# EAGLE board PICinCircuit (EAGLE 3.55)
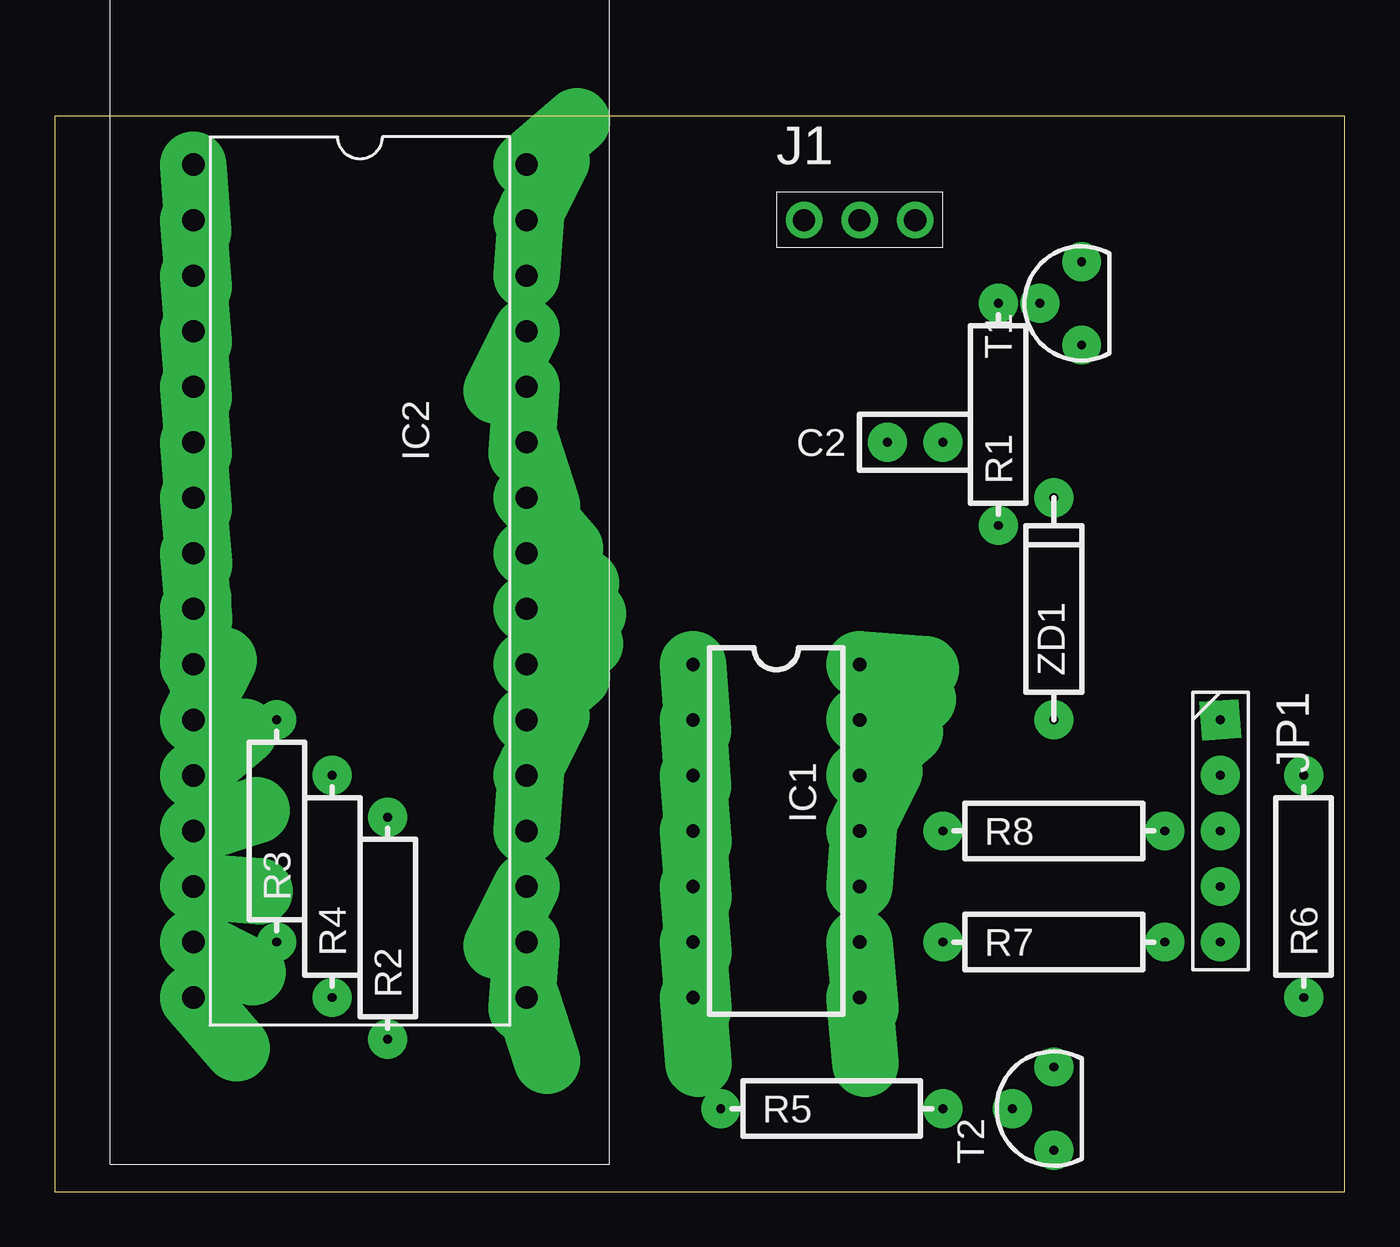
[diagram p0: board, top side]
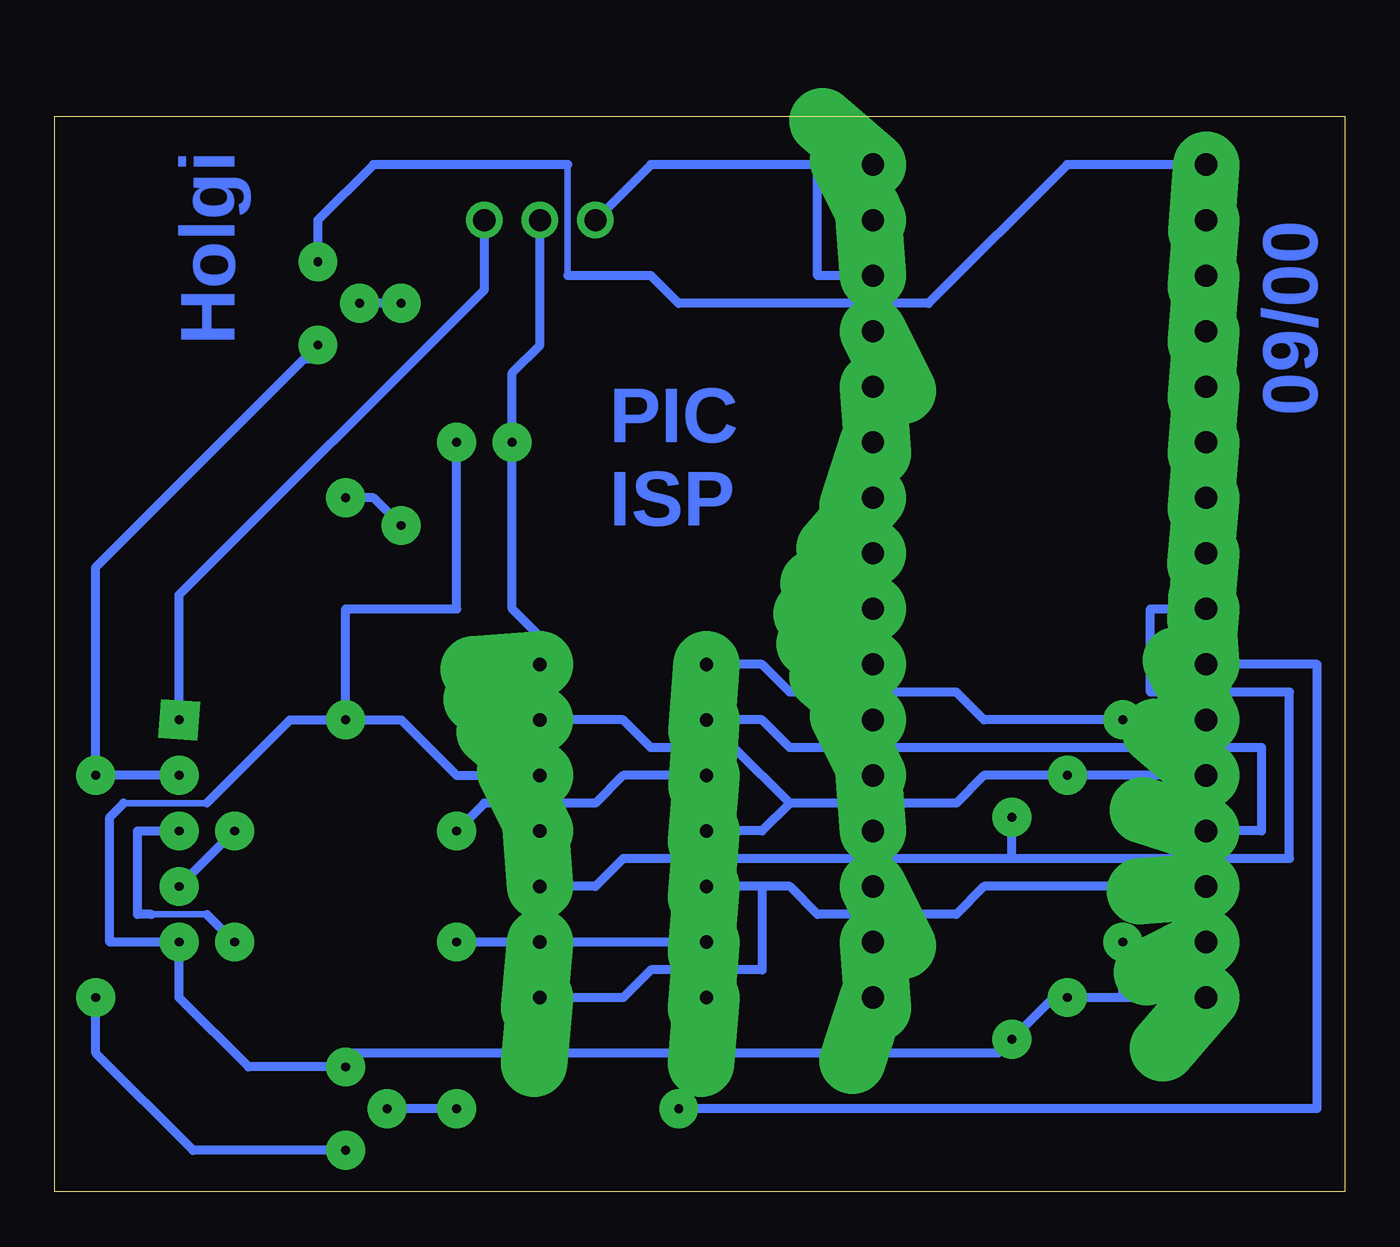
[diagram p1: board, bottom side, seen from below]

Size 59.03 x 49.2 mm. Coordinates in mm from the lower left corner, seen from the top.
Outline: 0,0 59.03,0 59.03,49.2 0,49.2 0,0
Copper layers used: Bottom

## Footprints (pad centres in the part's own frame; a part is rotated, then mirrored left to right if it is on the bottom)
RM2,5 = drill 0.406 pad 1.778 round:  0,0;  2.54,0
L-14B = drill 0.61 pad 3.048 offset:  0,0;  2.54,0;  5.08,0;  7.62,0;  10.16,0;  12.7,0;  15.24,0;  15.24,7.62;  12.7,7.62;  10.16,7.62;  7.62,7.62;  5.08,7.62;  2.54,7.62;  0,7.62
XTO_32 = drill 1.016 pad 3.048 offset:  0,0;  2.54,0;  15.24,0;  17.78,0;  5.08,0;  7.62,0;  12.7,0;  10.16,0;  20.32,0;  22.86,0;  25.4,0;  27.94,0;  30.48,0;  33.02,0;  35.56,0;  38.1,0;  38.1,15.24;  35.56,15.24;  33.02,15.24;  30.48,15.24;  27.94,15.24;  25.4,15.24;  22.86,15.24;  20.32,15.24;  17.78,15.24;  15.24,15.24;  12.7,15.24;  10.16,15.24;  7.62,15.24;  5.08,15.24;  2.54,15.24;  0,15.24
MPER_3 = drill 1.016 pad 1.676 round:  0,0;  2.54,0;  5.08,0
5 = drill 0.406 pad 1.778 square:  0,0 | drill 0.406 pad 1.778 round:  5.08,0;  10.16,0;  7.62,0;  2.54,0
S04 = drill 0.406 pad 1.778 round:  0,0;  10.16,0
92 = drill 0.406 pad 1.778 round:  -0.635,0;  1.27,1.905;  3.175,0
O04 = drill 0.406 pad 1.778 round:  0,0;  10.16,0

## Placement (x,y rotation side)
C2  100n  [RM2,5]  40.64,34.29 180 top
IC1  74HC126  [L-14B]  29.21,24.13 270 top
IC2  TEXTOEP_32  [XTO_32]  6.35,46.99 270 top
J1  JUMPER_3  [MPER_3]  34.29,44.45 0 top
JP1  PINHD-1X5  [5]  53.34,21.59 270 top
R1  10k  [S04]  43.18,30.48 90 top
R2  47k  [S04]  15.24,6.99 90 top
R3  47k  [S04]  10.16,11.43 90 top
R4  47k  [S04]  12.7,8.89 90 top
R5  10k  [S04]  30.48,3.81 0 top
R6  470  [S04]  57.15,8.89 90 top
R7  220  [S04]  40.64,11.43 0 top
R8  220  [S04]  40.64,16.51 0 top
T1  BC327  [92]  46.99,39.37 90 top
T2  BC547  [92]  45.72,2.54 90 top
ZD1  8v2  [O04]  45.72,21.59 90 top

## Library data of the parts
C2 IC1 JP1 R1-R8 T1 T2 ZD1 = holg_plt
IC2 = galeprom
J1 = holgnorm

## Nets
5V_EXT: J1. JP1.
5V_INT: IC2. J1.
+5V: C2. IC1. J1.
GND: C2. IC1. IC2. JP1. R2. R3. R4. T2. ZD1.
MCLR: JP1. R6. T1.
N$1: IC1. IC2. R2.
N$2: R6. T2.
N$3: IC1. IC2. R3.
N$4: IC1. IC2. R4.
N$5: R5. T2.
N$6: JP1. R8.
N$7: R1. T1.
N$8: R1. ZD1.
N$9: IC2. R5.
N$10: JP1. R7.
PB6: IC1. R8.
PB7: IC1. R7.
SCK: IC1. IC2.
SDA: IC1. IC2.
VPP: IC2. T1.

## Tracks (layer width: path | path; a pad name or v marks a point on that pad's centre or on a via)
5V_EXT
  Bottom 0.406: J1. 39.37,41.27 53.34,27.3 53.34,21.59
5V_INT
  Bottom 0.406: 34.29,44.45 31.75,46.99 24.13,46.99 | 24.13,46.99 IC2. | 24.13,46.99 24.13,41.91 21.59,41.91
+5V
  Bottom 0.406: IC1. 36.83,25.4 38.1,26.67 C2. 38.1,37.47 36.83,38.73 36.83,44.45
GND
  Bottom 0.305: 55.88,17.78 52.07,17.78
  Bottom 0.406: 40.64,34.29 40.64,26.67 45.72,26.67 45.72,21.59 | 55.88,17.78 56.52,17.14 56.52,11.43 53.34,11.43 53.34,8.89 50.16,5.71 T2. 45.72,6.35 29.21,6.35 | 29.21,6.35 29.21,8.89 | 6.35,8.89 10.16,8.89 | 10.16,8.89 10.16,11.43 | 10.16,8.89 12.7,8.89 13.34,8.89 15.24,6.99 15.88,6.35 29.21,6.35 | 52.07,17.78 48.26,21.59 45.72,21.59 | 36.83,19.05 40.64,19.05 43.18,21.59 45.72,21.59
MCLR
  Bottom 0.406: 46.99,38.73 46.99,38.1 47.62,38.1 57.15,28.57 R6. JP1.
N$1
  Bottom 0.406: 6.35,26.67 8.89,26.67 8.89,22.86 2.54,22.86 2.54,15.24 15.24,15.24 | 15.24,15.24 33.02,15.24 34.29,13.97 36.83,13.97 | 15.24,15.24 R2.
N$2
  Bottom 0.406: 57.15,8.89 57.15,6.35 52.7,1.91 45.72,1.91
N$3
  Bottom 0.406: 6.35,21.59 R3. 16.51,21.59 17.78,22.86 25.4,22.86 26.67,24.13 29.21,24.13
N$4
  Bottom 0.406: 6.35,19.05 R4. 16.51,19.05 17.78,17.78 25.4,17.78 | 29.21,16.51 26.67,16.51 25.4,17.78 | 25.4,17.78 27.94,20.32 31.75,20.32 33.02,21.59 36.83,21.59
N$5
  Bottom 0.406: R5. 43.81,3.81
N$6
  Bottom 0.406: 53.34,13.97 R8.
N$7
  Bottom 0.406: R1. 45.09,40.64
N$8
  Bottom 0.406: ZD1. 44.45,31.75 43.18,30.48
N$9
  Bottom 0.406: 6.35,24.13 1.27,24.13 1.27,3.81 30.48,3.81
N$10
  Bottom 0.305: 52.07,12.7 54.61,12.7
  Bottom 0.406: 53.34,16.51 55.24,16.51 55.24,12.7 54.61,12.7 | R7. 52.07,12.7
PB6
  Bottom 0.406: 29.21,19.05 33.02,19.05 34.29,17.78 39.37,17.78 40.64,16.51
PB7
  Bottom 0.406: 29.21,11.43 36.83,11.43 40.64,11.43
SCK
  Bottom 0.406: 6.35,16.51 3.81,16.51 3.81,20.32 25.4,20.32 26.67,21.59 29.21,21.59
SDA
  Bottom 0.406: 6.35,13.97 16.51,13.97 17.78,12.7 24.13,12.7 25.4,13.97 26.67,13.97 | 26.67,13.97 29.21,13.97 | 26.67,13.97 26.67,10.16 31.75,10.16 33.02,8.89 36.83,8.89
VPP
  Bottom 0.305: 35.56,41.91 35.56,46.99
  Bottom 0.406: 6.35,46.99 12.7,46.99 19.05,40.64 30.48,40.64 31.75,41.91 35.56,41.91 | 35.56,46.99 44.45,46.99 46.99,44.45 T1.

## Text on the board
Bottom: Holgi | 09/00 | PIC | ISP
